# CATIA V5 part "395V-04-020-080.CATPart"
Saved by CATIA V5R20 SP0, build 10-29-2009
Part number: 395V-04-020-080
Source: Unknown
Property "A": "0.000"
Property "ARTICLENO": "395V-04-020-080"
Property "BOMINFO": "395V-04-020-080"
Property "CODE": "395V-04-020-080"
Property "D": "16.000"
Property "D1": "9.500"
Property "D2": "14.500"
Property "D3": "24.000"
Property "FORM": "A"
Property "L": "80.000"
Property "L1": "10.000"
Property "L2": "34.000"
Property "L3": "20.000"
Property "L4": "6.000"
Property "LINA": "395V-04-020-080"
Property "MAXLOAD": "320 Kg"
Property "MDW": "640 Kg"
Property "NB": "395V-04-020-080"
Property "NBSYN": "$CODE."
Property "NN": "395V"
Property "NT": "VDI 3366 Lifting Brackets"
Property "SUPPLIER": "CF"
Property "T": "9.000"
Property "W": "20.000"
Bounding box of the stored display mesh (mm): x -10 to 10, y 0 to 80, z -10 to 10
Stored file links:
  C:\Users\Utente\Desktop\3D files 395V\395V-04-020-080.CATPart
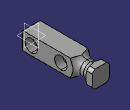
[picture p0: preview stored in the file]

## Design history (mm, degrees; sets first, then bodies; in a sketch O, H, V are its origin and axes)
Body1 "Geometry.1" (main body)
  Solid1 "395V-04-020-080.catpart": solid without history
